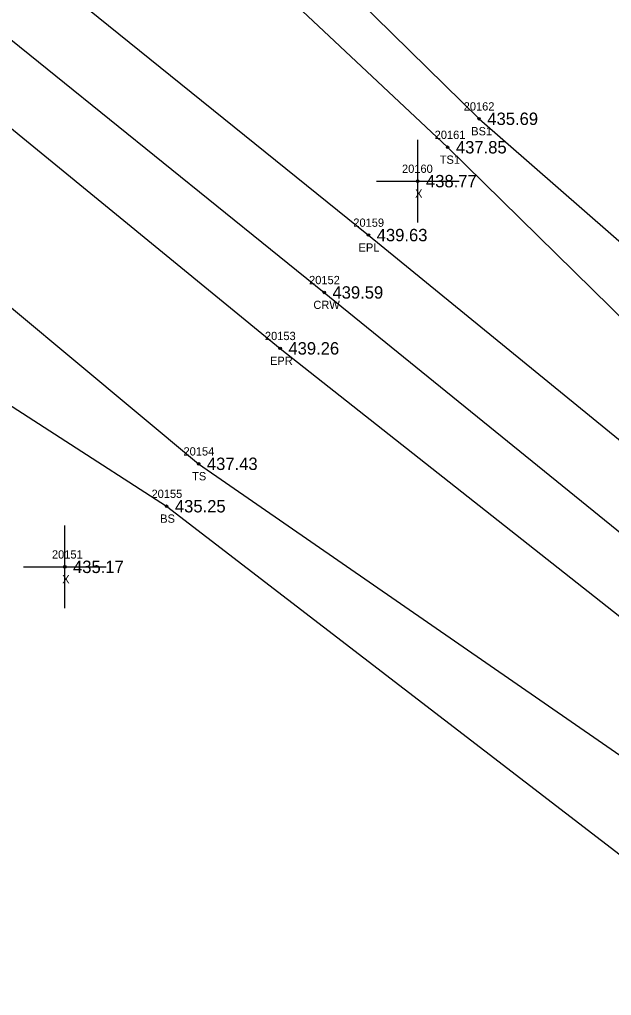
# Model space of a CAD drawing. Extents: x 1613836 to 1615109, y 777151 to 778248.
# Drawn here: x 1614329.5 to 1614401.1, y 777687.6 to 777805.7 of the extents above; entities that cross this region are included whole.
import ezdxf

# ---------------------------------------------------------------- set-up
doc = ezdxf.new("R2010")
doc.units = 0
for name, color, linetype in [('RD_DTM_BkLn1', 7, 'Continuous'), ('RD_DTM_BkLn2', 7, 'Continuous'), ('RD_DTM_BkLn_txCode', 7, 'Continuous'), ('RD_EX_Misc', 7, 'Continuous'), ('RD_EX_Misc_txCode', 7, 'Continuous'), ('RD_EX_Road', 7, 'Continuous'), ('RD_EX_Road_txCode', 7, 'Continuous'), ('RD_EX_TX_Misc_ELEV', 7, 'Continuous'), ('RD_EX_TX_Road_ELEV', 7, 'Continuous'), ('RD_HC_Survey_ELEV', 7, 'Continuous'), ('RD_HC_Survey_txCode', 7, 'Continuous'), ('RD_SMD_Locator', 7, 'Continuous')]:
    doc.layers.add(name, color=color, linetype=linetype)

msp = doc.modelspace()

# ---------------------------------------------------------------- linework, layer by layer
at = {"layer": 'RD_DTM_BkLn1'}
msp.add_lwpolyline([(1613865.21, 778095.86), (1613910.73, 778075.92), (1613956.18, 778054.99), (1614000.73, 778032.51), (1614044.52, 778008.68), (1614087.21, 777982.81), (1614129.12, 777955.82), (1614169.63, 777926.64), (1614209.9, 777896.76), (1614249.35, 777866.21), (1614288.43, 777835.55), (1614366.39, 777772.65), (1614443.98, 777709.72)], dxfattribs=at)
at = {"layer": 'RD_DTM_BkLn2'}
for points in [[(1613870.65, 778107.91), (1613917.36, 778089.81), (1613963.47, 778068.53), (1614008.76, 778046.32), (1614052.42, 778023.01), (1614094.96, 777996.37), (1614137.71, 777969), (1614179.06, 777940.06), (1614196.49, 777927.41), (1614202.23, 777922.93), (1614210.94, 777920.91), (1614226.4, 777922.61), (1614267.62, 777889.85), (1614307.16, 777859.76), (1614381.32, 777790.21), (1614451.43, 777721.4), (1614453.49, 777722.08), (1614455.33, 777720.48), (1614437.07, 777696.16)], [(1613860.36, 778083.39), (1613904.96, 778062.9), (1613950.73, 778042.94), (1613994.86, 778021.25), (1614038.25, 777997.65), (1614118.58, 777941.84), (1614160.54, 777914.82), (1614182.29, 777896.21), (1614189.42, 777895.9), (1614196.65, 777882.72), (1614195.5, 777875.76), (1614231.56, 777844.86), (1614271.92, 777815.6), (1614305.89, 777789.49), (1614313.92, 777782.98), (1614351.2, 777751.93), (1614424.47, 777701.24), (1614433.25, 777695.63), (1614437.07, 777696.16)], [(1614263.34, 777907.48), (1614273.9, 777898.51), (1614311.56, 777865.81), (1614385.12, 777793.65), (1614458.7, 777729.38), (1614464.37, 777721.53)], [(1614308.68, 777771.7), (1614347.33, 777746.8), (1614414.57, 777695.15), (1614432.9, 777688.24), (1614439.87, 777687.64), (1614444.54, 777689.78)]]:
    msp.add_lwpolyline(points, dxfattribs=at)
at = {"layer": 'RD_EX_Misc'}
for p, q in [((1614377.7, 777781.11), (1614377.7, 777791.11)), ((1614372.7, 777786.11), (1614382.7, 777786.11)), ((1614335.01, 777734.47), (1614335.01, 777744.47)), ((1614330.01, 777739.47), (1614340.01, 777739.47))]:
    msp.add_line(p, q, dxfattribs=at)
at = {"layer": 'RD_EX_Road'}
for points in [[(1613868.87, 778104.15), (1613915.02, 778083.82), (1613960.16, 778062.2), (1614004.58, 778040.28), (1614048.84, 778015.98), (1614091.38, 777990.08), (1614134.36, 777962.6), (1614174.73, 777933.48), (1614192.07, 777920.58), (1614215.93, 777904.23), (1614254.59, 777873.05), (1614293.82, 777842.42), (1614371.74, 777779.59), (1614449.33, 777716.3), (1614443.98, 777709.72), (1614439.38, 777704.09)], [(1613862.14, 778087.92), (1613908.12, 778068.22), (1613952.96, 778047.38), (1613997, 778025.09), (1614041.16, 778001.63), (1614124.35, 777949.06), (1614164.51, 777920.91), (1614187.11, 777904.29), (1614205.27, 777889.82), (1614244.49, 777859.52), (1614283.42, 777829.45), (1614361.06, 777765.89), (1614439.38, 777704.09)]]:
    msp.add_lwpolyline(points, dxfattribs=at)
at = {"layer": 'RD_SMD_Locator'}
for centre in [(1614385.12, 777793.65), (1614381.32, 777790.21), (1614377.7, 777786.11), (1614371.74, 777779.59), (1614366.39, 777772.65), (1614361.06, 777765.89), (1614351.2, 777751.93), (1614347.33, 777746.8), (1614335.01, 777739.47)]:
    msp.add_circle(centre, 0.15, dxfattribs=at)

# ---------------------------------------------------------------- texts
at = {"layer": 'RD_DTM_BkLn_txCode'}
for s, p in [('20162', (1614383.26, 777794.65)), ('BS1', (1614384.17, 777791.65)), ('20161', (1614379.75, 777791.21)), ('TS1', (1614380.36, 777788.21)), ('20154', (1614349.37, 777752.93)), ('TS', (1614350.41, 777749.93)), ('20155', (1614345.5, 777747.8)), ('BS', (1614346.55, 777744.8))]:
    msp.add_text(s, height=1, dxfattribs=at).set_placement(p)
at = {"layer": 'RD_EX_Misc_txCode'}
for s, p in [('20160', (1614375.8, 777787.11)), ('X', (1614377.38, 777784.11)), ('20151', (1614333.46, 777740.47)), ('X', (1614334.7, 777737.47))]:
    msp.add_text(s, height=1, dxfattribs=at).set_placement(p)
at = {"layer": 'RD_EX_Road_txCode'}
for s, p in [('20159', (1614369.91, 777780.59)), ('EPL', (1614370.54, 777777.59)), ('20153', (1614359.22, 777766.89)), ('EPR', (1614359.83, 777763.89))]:
    msp.add_text(s, height=1, dxfattribs=at).set_placement(p)
at = {"layer": 'RD_EX_TX_Misc_ELEV'}
for s, p in [('435.69', (1614386.12, 777792.9)), ('437.85', (1614382.32, 777789.46)), ('438.77', (1614378.7, 777785.36)), ('437.43', (1614352.2, 777751.18)), ('435.25', (1614348.33, 777746.05)), ('435.17', (1614336.01, 777738.72))]:
    msp.add_text(s, height=1.5, dxfattribs=at).set_placement(p)
at = {"layer": 'RD_EX_TX_Road_ELEV'}
for s, p in [('439.63', (1614372.74, 777778.84)), ('439.26', (1614362.06, 777765.14))]:
    msp.add_text(s, height=1.5, dxfattribs=at).set_placement(p)
at = {"layer": 'RD_HC_Survey_ELEV'}
msp.add_text('439.59', height=1.5, dxfattribs=at).set_placement((1614367.39, 777771.9))
at = {"layer": 'RD_HC_Survey_txCode'}
for s, p in [('20152', (1614364.56, 777773.65)), ('CRW', (1614365.08, 777770.65))]:
    msp.add_text(s, height=1, dxfattribs=at).set_placement(p)

doc.saveas('drawing.dxf')
